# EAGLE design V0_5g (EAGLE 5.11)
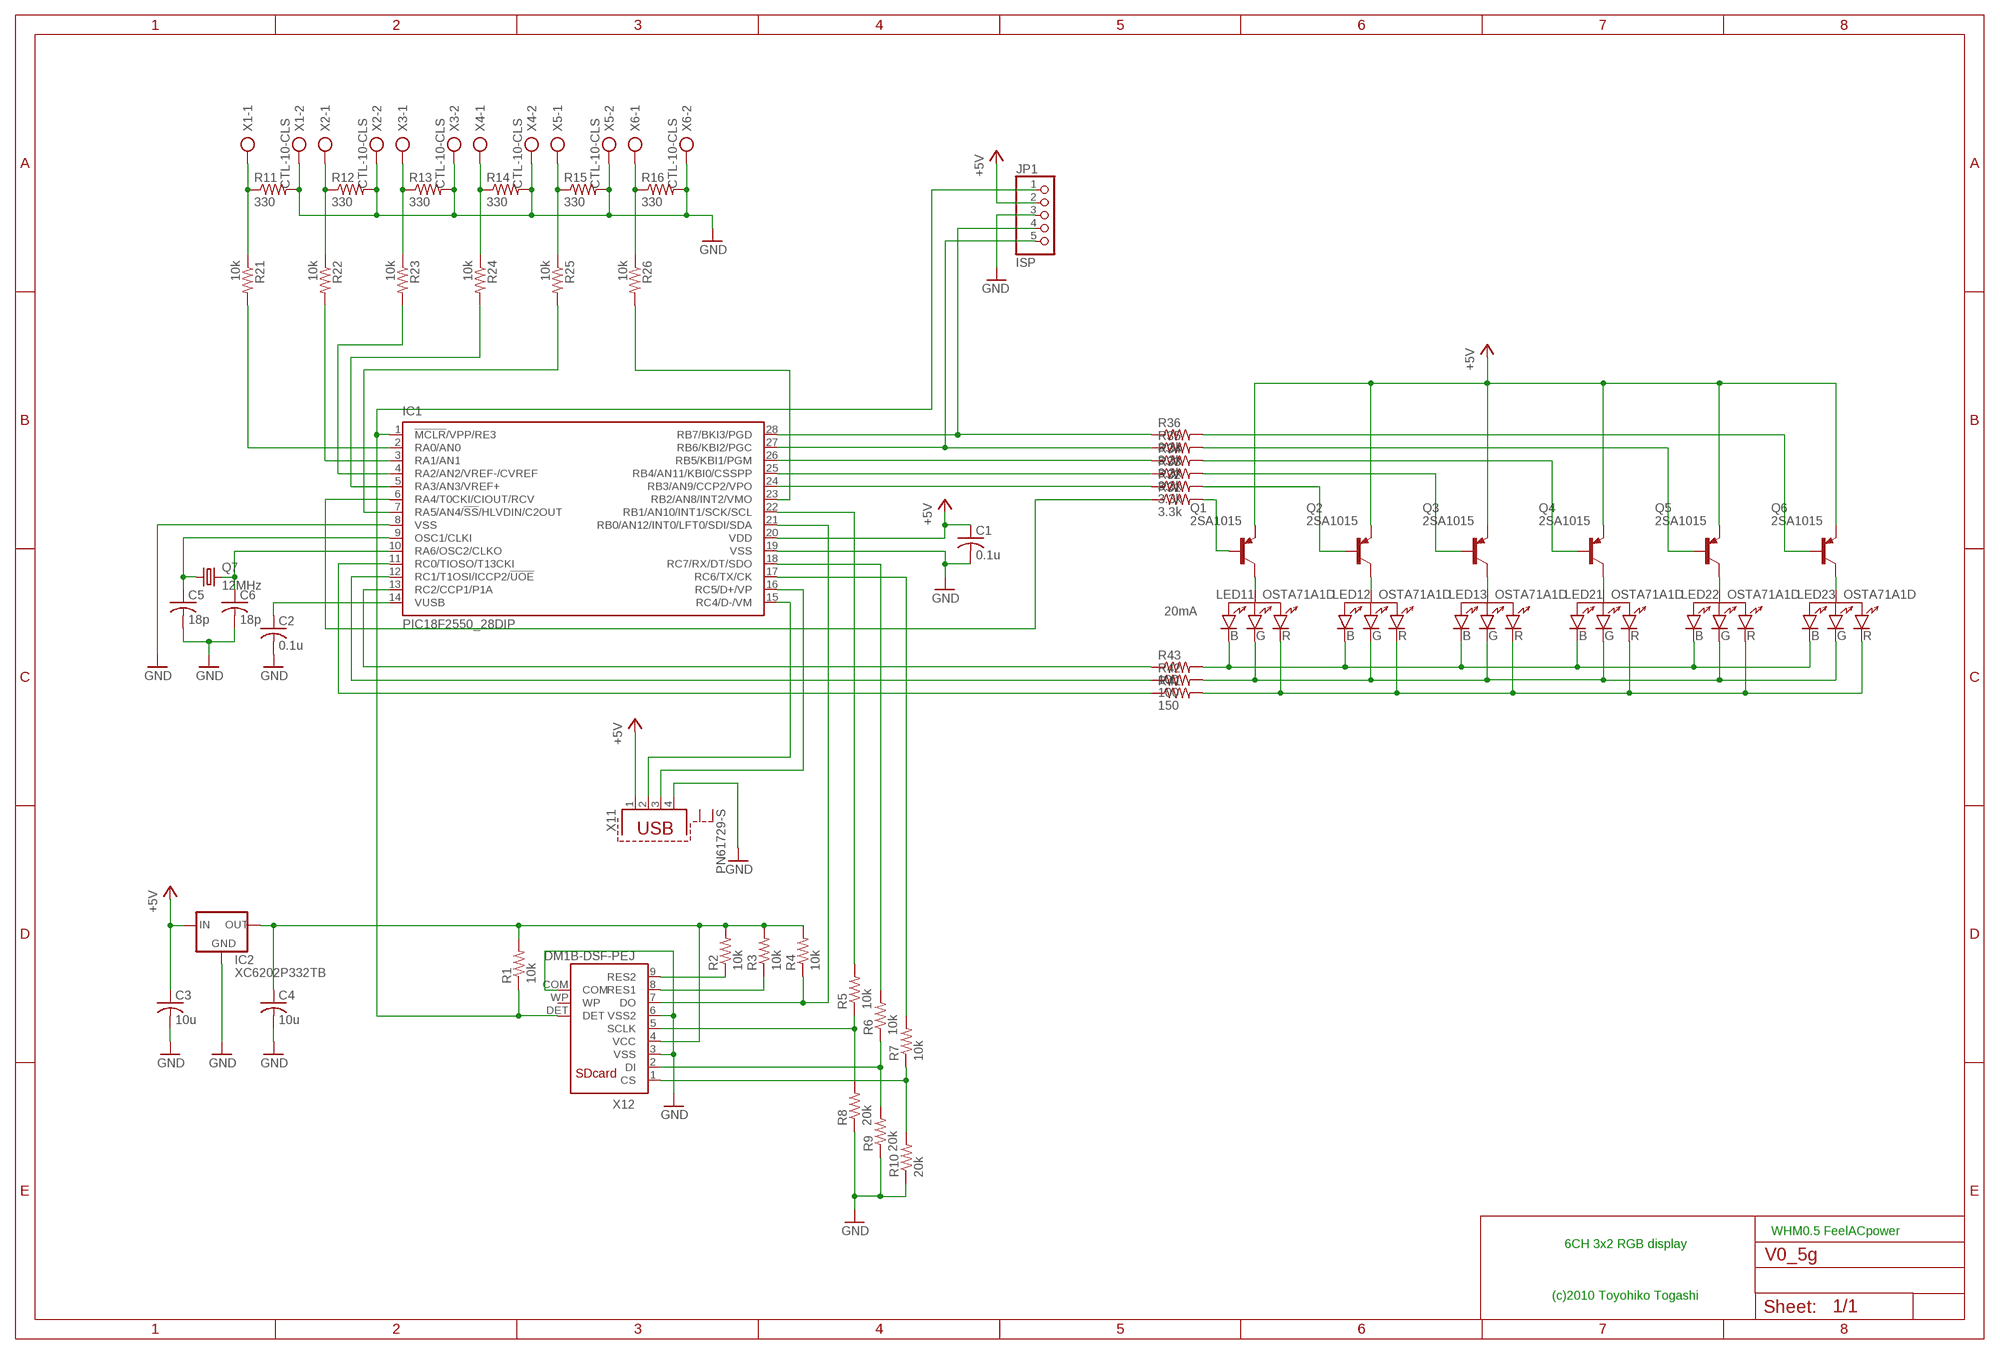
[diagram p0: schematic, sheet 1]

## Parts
C1  0.1u  C-US025-025X050  [C025-025X050]
C2  0.1u  C-US025-025X050  [C025-025X050]
C3  10u  C-US025-025X050  [C025-025X050]
C4  10u  C-US025-025X050  [C025-025X050]
C5  18p  C-US025-024X044  [C025-024X044]
C6  18p  C-US025-024X044  [C025-024X044]
IC1  PIC18F2550_28DIP  [DIL28-3]
IC2  XC6202P332TB  78LXX  [78LXX]
JP1  ISP  PINHD-1X5  [1X05]
LED11  OSTA71A1D  [FLUX-LED]
LED12  OSTA71A1D  [FLUX-LED]
LED13  OSTA71A1D  [FLUX-LED]
LED21  OSTA71A1D  [FLUX-LED]
LED22  OSTA71A1D  [FLUX-LED]
LED23  OSTA71A1D  [FLUX-LED]
Q1  2SA1015  BF421  [TO92-BCE]
Q2  2SA1015  BF421  [TO92-BCE]
Q3  2SA1015  BF421  [TO92-BCE]
Q4  2SA1015  BF421  [TO92-BCE]
Q5  2SA1015  BF421  [TO92-BCE]
Q6  2SA1015  BF421  [TO92-BCE]
Q7  12MHz  CRYSTALHC49S  [HC49/S]
R1  10k  R-US_0204/7  [0204/7]
R2  10k  R-US_0204/7  [0204/7]
R3  10k  R-US_0204/7  [0204/7]
R4  10k  R-US_0204/7  [0204/7]
R5  10k  R-US_0204/7  [0204/7]
R6  10k  R-US_0204/7  [0204/7]
R7  10k  R-US_0204/7  [0204/7]
R8  20k  R-US_0204/7  [0204/7]
R9  20k  R-US_0204/7  [0204/7]
R10  20k  R-US_0204/7  [0204/7]
R11  330  R-US_0204/7  [0204/7]
R12  330  R-US_0204/7  [0204/7]
R13  330  R-US_0204/7  [0204/7]
R14  330  R-US_0204/7  [0204/7]
R15  330  R-US_0204/7  [0204/7]
R16  330  R-US_0204/7  [0204/7]
R21  10k  R-US_0204/7  [0204/7]
R22  10k  R-US_0204/7  [0204/7]
R23  10k  R-US_0204/7  [0204/7]
R24  10k  R-US_0204/7  [0204/7]
R25  10k  R-US_0204/7  [0204/7]
R26  10k  R-US_0204/7  [0204/7]
R31  3.3k  R-US_0204/5  [0204/5]
R32  3.3k  R-US_0204/5  [0204/5]
R33  3.3k  R-US_0204/5  [0204/5]
R34  3.3k  R-US_0204/7  [0204/7]
R35  3.3k  R-US_0204/7  [0204/7]
R36  3.3k  R-US_0204/7  [0204/7]
R41  150  R-US_0204/7  [0204/7]
R42  100  R-US_0204/7  [0204/7]
R43  100  R-US_0204/7  [0204/7]
X1  CTL-10-CLS  AK500/2  [AK500/2]
X2  CTL-10-CLS  AK500/2  [AK500/2]
X3  CTL-10-CLS  AK500/2  [AK500/2]
X4  CTL-10-CLS  AK500/2  [AK500/2]
X5  CTL-10-CLS  AK500/2  [AK500/2]
X6  CTL-10-CLS  AK500/2  [AK500/2]
X11  PN61729-S  [PN61729-S]
X12  DM1B-DSF-PEJ  [DM1B]

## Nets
+5V: C1.1 C3.1 IC1.20(VDD) IC2.IN JP1.2 Q1.E Q2.E Q3.E Q4.E Q5.E Q6.E X11.1
GND: C1.2 C2.2 C3.2 C4.2 C5.2 C6.2 IC1.8(VSS) IC1.19(VSS) IC2.GND JP1.3 R8.1 R9.1 R10.1 R11.2 R12.2 R13.2 R14.2 R15.2 R16.2 X1.2 X2.2 X3.2 X4.2 X5.2 X6.2 X11.4 X12.3(VSS) X12.6(VSS2) X12.COM
N$1: IC1.7(RA5/AN4/!SS!/HLVDIN/C2OUT) R25.2
N$2: IC1.5(RA3/AN3/VREF+) R24.2
N$3: IC1.4(RA2/AN2/VREF-/CVREF) R23.2
N$4: IC1.3(RA1/AN1) R22.2
N$5: C4.1 IC2.OUT R1.2 R2.2 R3.2 R4.2 X12.4(VCC)
N$6: R5.1 R8.2 X12.5(SCLK)
N$7: IC1.21(RB0/AN12/INT0/LFT0/SDI/SDA) R4.1 X12.7(DO)
N$8: R6.1 R9.2 X12.2(DI)
N$9: R7.1 R10.2 X12.1(CS)
N$10: IC1.1(!MCLR!/VPP/RE3) JP1.1 R1.1 X12.DET
N$11: LED21.P$1 Q4.C
N$13: LED22.P$1 Q5.C
N$14: IC1.25(RB4/AN11/KBI0/CSSPP) R33.1
N$15: LED12.P$1 Q2.C
N$16: IC1.15(RC4/D-/VM) X11.2
N$17: IC1.16(RC5/D+/VP) X11.3
N$18: LED13.P$1 Q3.C
N$19: LED23.P$1 Q6.C
N$20: IC1.22(RB1/AN10/INT1/SCK/SCL) R5.2
N$21: IC1.18(RC7/RX/DT/SDO) R6.2
N$22: IC1.17(RC6/TX/CK) R7.2
N$23: IC1.6(RA4/T0CKI/CIOUT/RCV) R31.1
N$24: Q4.B R34.2
N$25: IC1.11(RC0/TIOSO/T13CKI) R41.1
N$26: IC1.26(RB5/KBI1/PGM) R34.1
N$27: IC1.12(RC1/T1OSI/ICCP2/!UOE) R42.1
N$28: IC1.13(RC2/CCP1/P1A) R43.1
N$29: IC1.23(RB2/AN8/INT2/VMO) R26.2
N$30: IC1.28(RB7/BKI3/PGD) JP1.4 R36.1
N$31: IC1.27(RB6/KBI2/PGC) JP1.5 R35.1
N$33: Q1.B R31.2
N$35: Q2.B R32.2
N$37: R16.1 R26.1 X6.1
N$38: R15.1 R25.1 X5.1
N$39: R14.1 R24.1 X4.1
N$40: R13.1 R23.1 X3.1
N$41: R12.1 R22.1 X2.1
N$42: R2.1 X12.9(RES2)
N$43: R3.1 X12.8(RES1)
N$44: R11.1 R21.1 X1.1
N$45: Q3.B R33.2
N$46: Q5.B R35.2
N$47: C6.1 IC1.10(RA6/OSC2/CLKO) Q7.2
N$48: Q6.B R36.2
N$49: C5.1 IC1.9(OSC1/CLKI) Q7.1
N$50: IC1.2(RA0/AN0) R21.2
N$52: C2.1 IC1.14(VUSB)
N$55: LED11.P$1 Q1.C
N$56: LED11.P$2 LED12.P$2 LED13.P$2 LED21.P$2 LED22.P$2 LED23.P$2 R43.2
N$58: LED11.P$4 LED12.P$4 LED13.P$4 LED21.P$4 LED22.P$4 LED23.P$4 R41.2
N$59: LED11.P$3 LED12.P$3 LED13.P$3 LED21.P$3 LED22.P$3 LED23.P$3 R42.2
N$65: IC1.24(RB3/AN9/CCP2/VPO) R32.1
Unconnected: X11.S1 X11.S2 X12.WP

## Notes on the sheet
- 20mA
- WHM0.5 FeelACpower
- 6CH 3x2 RGB display
- (c)2010 Toyohiko Togashi

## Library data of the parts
C1-C6 = rcl:C-US: CAPACITOR, American symbol
IC1 = microchip:PIC18F2*_28: USB Microcontrollers with nanoWatt Technology High-Performance, Enhanced Flash, 28/40/44-Pin, Source: http://ww1.microchip.com/downloads/en/devicedoc/39632c.pdf
IC2 = v-reg:78LXX: VOLTAGE REGULATOR
JP1 = pinhead:PINHD-1X5: PIN HEADER
LED11-LED13 LED21-LED23 = TOG:OSTA71A1D: Super Flux RGB LED
Q1-Q6 = transistor-pnp:BF421*: PNP Transistror
Q7 = crystal:CRYSTAL: CRYSTAL; OC_FARNELL: 1667008; OC_NEWARK: unknown
R1-R16 R21-R26 R31-R36 R41-R43 = rcl:R-US_: RESISTOR, American symbol
X1-X6 = con-ptr500:AK500/2: CONNECTOR
X11 = con-berg:PN61729-S: BERG USB connector
X12 = TOG:DM1B-DSF-PEJ: SDcard connector reverse type HIROSE

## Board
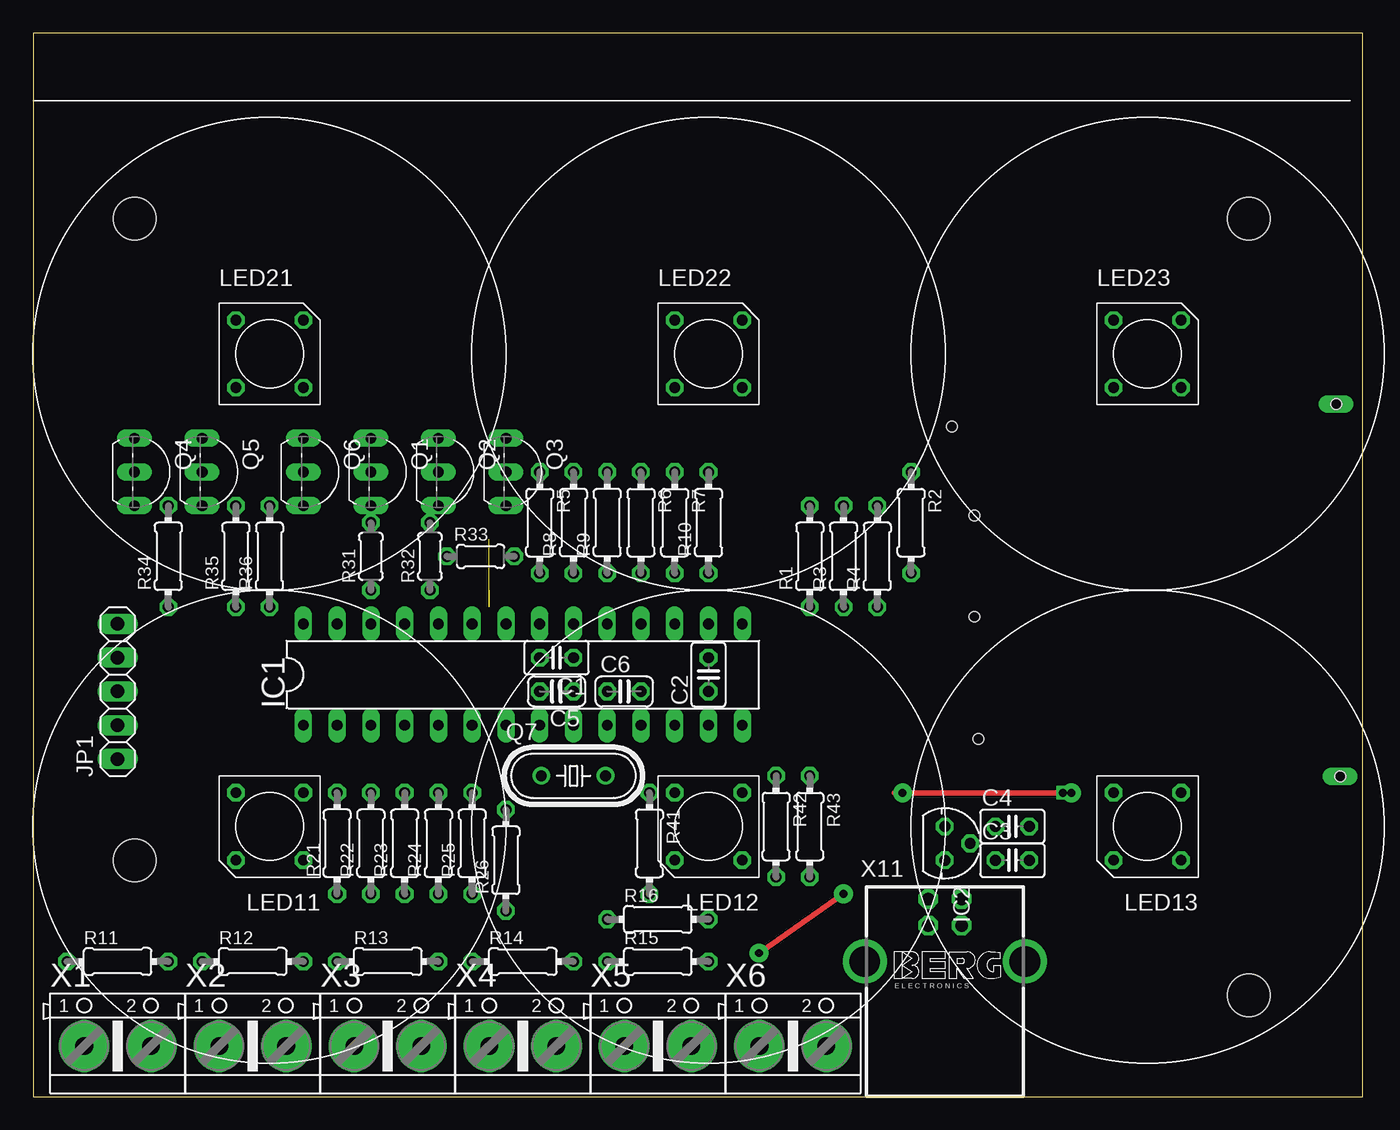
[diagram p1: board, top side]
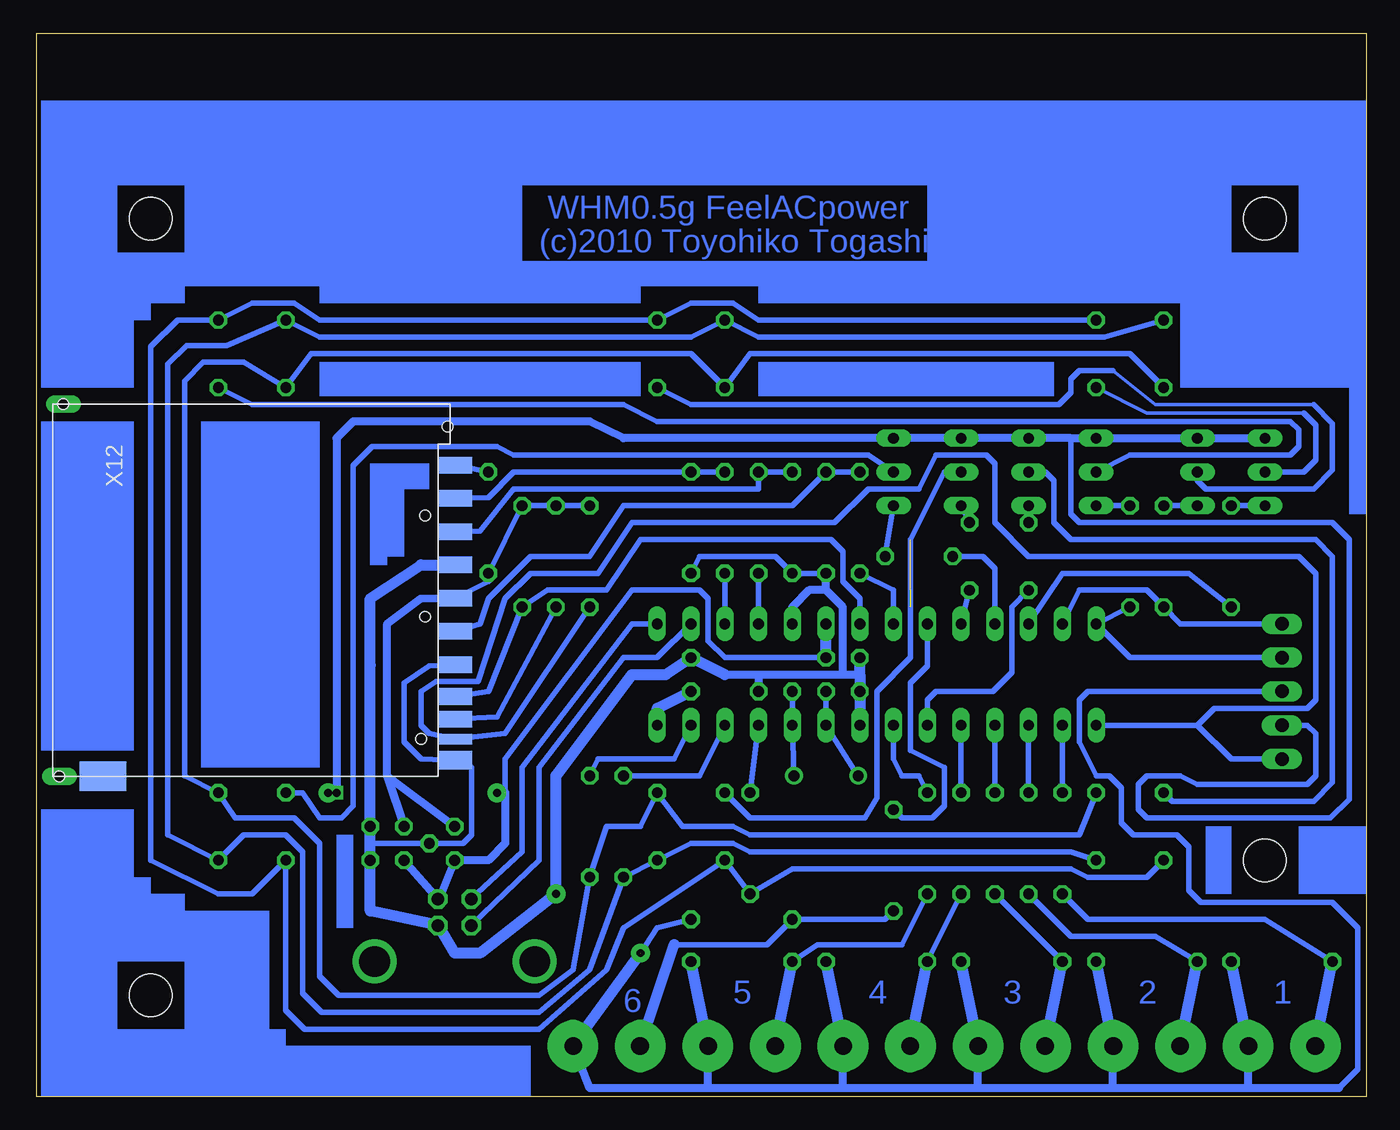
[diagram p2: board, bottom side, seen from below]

Size 100 x 80 mm. Coordinates in mm from the lower left corner, seen from the top.
Outline: 0,0 100,0 100,80 0,80 0,0
Copper layers (1*16): Top 0.035mm / dielectric 1.5mm / Bottom 0.035mm
Design rules "default": minimum track width 10mil, minimum drill 24mil, track to track 8mil, track to pad 8mil, pad to pad 8mil, via to via 8mil, smd to smd 8mil, copper to edge 40mil, drill to drill 8mil, minimum pad ring 10mil, minimum via ring 8mil, stop-mask expansion 4mil, vias tented up to drill 0mil, thermal gap 10mil
Holes 3.2 mm at 7.62,17.78 91.44,7.62 91.44,66.04 7.62,66.04

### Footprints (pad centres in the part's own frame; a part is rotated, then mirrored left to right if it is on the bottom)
C025-025X050 = drill 0.813 octagon: 1 -1.27,0; 2 1.27,0
C025-024X044 = drill 0.813 octagon: 1 -1.27,0; 2 1.27,0
DIL28-3 = drill 0.813 long: 1 -16.51,-3.81; 2 -13.97,-3.81; 3 -11.43,-3.81; 4 -8.89,-3.81; 5 -6.35,-3.81; 6 -3.81,-3.81; 7 -1.27,-3.81; 8 1.27,-3.81; 9 3.81,-3.81; 10 6.35,-3.81; 11 8.89,-3.81; 12 11.43,-3.81; 13 13.97,-3.81; 14 16.51,-3.81; 15 16.51,3.81; 16 13.97,3.81; 17 11.43,3.81; 18 8.89,3.81; 19 6.35,3.81; 20 3.81,3.81; 21 1.27,3.81; 22 -1.27,3.81; 23 -3.81,3.81; 24 -6.35,3.81; 25 -8.89,3.81; 26 -11.43,3.81; 27 -13.97,3.81; 28 -16.51,3.81
78LXX = drill 0.813 octagon: GND 0,1.905; IN 1.27,0; OUT -1.27,0
1X05 = drill 1.016 long: 1 -5.08,0; 2 -2.54,0; 3 0,0; 4 2.54,0; 5 5.08,0
FLUX-LED = drill 0.8 octagon: P$1 2.54,-2.54; P$2 -2.54,-2.54; P$3 -2.54,2.54; P$4 2.54,2.54
TO92-BCE = drill 0.813 long: B 2.54,0; C 0,0; E -2.54,0
HC49/S = drill 0.813 round: 1 -2.413,0; 2 2.413,0
0204/7 = drill 0.813 octagon: 1 -3.81,0; 2 3.81,0
0204/5 = drill 0.813 octagon: 1 -2.54,0; 2 2.54,0
AK500/2 = drill 1.321 long: 1 -2.515,0; 2 2.515,0
PN61729-S = drill 0.95 octagon: 1 1.25,4.71; 2 -1.25,4.71; 3 -1.25,2.71; 4 1.25,2.71 | drill 2.3 pad 2.9 round: S1 -6.02,0; S2 6.02,0
DM1B = smd 1.25 x 2.5: 1 -6.9,15.3; 2 -4.4,15.3; 3 -1.9,15.3; 4 0.6,15.3; 5 3.1,15.3; 6 5.6,15.3; 7 8,15.3; 8 9.7,15.3; 9 -9.4,15.3 | smd 1.4 x 2.5: COM 12.8,15.3 | smd 0.8 x 2.5: DET 11.2,15.3 | drill 0.8 pad 1.2 long: P$17 14,-14.5 | drill 0.8 pad 1.27 long: P$18 -14,-14.2 | smd 2.2 x 3.5: WP 14,-11.2 | hole 0.8: -12.3,14.7; -5.6,13; 2,13; 11.2,12.7; -14,-14.2; 14,-14.5

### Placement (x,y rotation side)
C1  39.37,33.02 180 top
C2  50.8,31.75 90 top
C3  73.66,17.78 0 top
C4  73.66,20.32 0 top
C5  39.37,30.48 180 top
C6  44.45,30.48 0 top
IC1  36.83,31.75 0 top
IC2  68.58,19.05 270 top
JP1  6.35,30.48 90 top
LED11  17.78,20.32 180 top
LED12  50.8,20.32 180 top
LED13  83.82,20.32 180 top
LED21  17.78,55.88 0 top
LED22  50.8,55.88 0 top
LED23  83.82,55.88 0 top
Q1  25.4,46.99 270 top
Q2  30.48,46.99 270 top
Q3  35.56,46.99 270 top
Q4  7.62,46.99 270 top
Q5  12.7,46.99 270 top
Q6  20.32,46.99 270 top
Q7  40.64,24.13 0 top
R1  58.42,40.64 90 top
R2  66.04,43.18 270 top
R3  60.96,40.64 90 top
R4  63.5,40.64 90 top
R5  38.1,43.18 270 top
R6  45.72,43.18 270 top
R7  48.26,43.18 270 top
R8  40.64,43.18 90 top
R9  43.18,43.18 90 top
R10  50.8,43.18 90 top
R11  6.35,10.16 0 top
R12  16.51,10.16 0 top
R13  26.67,10.16 0 top
R14  36.83,10.16 0 top
R15  46.99,10.16 0 top
R16  46.99,13.34 0 top
R21  22.86,19.05 90 top
R22  25.4,19.05 90 top
R23  27.94,19.05 90 top
R24  30.48,19.05 90 top
R25  33.02,19.05 90 top
R26  35.56,17.78 90 top
R31  25.4,40.64 90 top
R32  29.84,40.64 90 top
R33  33.66,40.64 0 top
R34  10.16,40.64 90 top
R35  15.24,40.64 90 top
R36  17.78,40.64 90 top
R41  46.35,19.05 270 top
R42  55.88,20.32 270 top
R43  58.42,20.32 270 top
X1  6.35,3.81 0 top
X2  16.51,3.81 0 top
X3  26.67,3.81 0 top
X4  36.83,3.81 0 top
X5  46.99,3.81 0 top
X6  57.15,3.81 0 top
X11  68.58,10.16 0 top
X12  83.82,38.1 270 bottom

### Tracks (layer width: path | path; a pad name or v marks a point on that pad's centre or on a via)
+5V  (via drill 0.6)  (1 unrouted)
  Top 0.406: v77.47,22.86 64.77,22.86
  Bottom 0.406: C1.1 48.26,33.02 49.53,34.29 49.53,37.47 50.16,38.1 55.24,38.1 64.77,25.4 64.77,22.86 | JP1.2 4.45,27.94 3.81,27.3 3.81,24.13 4.45,23.5 12.7,23.5 13.97,24.13 16.51,24.13 17.14,23.5 17.14,21.59 16.51,20.95 2.69,20.95 1.27,22.38 1.27,41.91 2.54,43.18 21.59,43.18 22.23,43.81 22.23,49.53 | 69.85,14.87 X11.1
  Bottom 0.61: Q4.E Q5.E Q6.E 22.23,49.53 Q1.E Q2.E Q3.E 55.88,49.53 58.42,50.8 76.2,50.8 77.47,49.53 v77.47,22.86 | 69.85,14.87 69.85,14.61 IC2.IN 66.04,17.78 64.77,19.05 64.77,22.86 | X11.1 C3.1
  Bottom 0.813: C1.1 IC1.20
GND  (via drill 0.6)  (1 unrouted)
  Top 0.406: 54.61,10.79 v60.96,15.24
  Bottom 0.406: 74.93,19.05 IC2.GND 67.94,19.05 67.31,19.68 67.31,24.77 X12.COM 71.12,25.4 72.39,26.67 72.39,31.11 70.48,32.38 X12.6 | R8.1 R9.1 44.45,40.64 50.16,40.64 R10.1 | JP1.3 20.95,30.48 21.59,29.84 21.59,26.67 20.32,24.13 19.31,24.13 18.41,23.23 18.41,20.58 17.52,19.68 14.23,19.68 13.34,18.79 13.34,15.5 12.44,14.61 2.54,14.61 0.64,12.7 0.64,2.06 2.06,0.64 | 54.61,10.79 53.34,12.7 R16.2
  Bottom 0.61: 8.89,0.64 X1.2 | 8.89,0.64 19.05,0.64 | 19.05,0.64 29.21,0.64 | 29.21,0.64 39.37,0.64 | 39.37,0.64 49.53,0.64 | 49.53,0.64 58.42,0.64 X6.2 | 19.05,0.64 X2.2 | 29.21,0.64 X3.2 | 39.37,0.64 X4.2 | 49.53,0.64 X5.2 | 2.06,0.64 8.89,0.64 | 48.26,31.75 45.72,31.75 | 45.72,31.75 C6.2 | 39.37,31.75 38.1,31.75 | 45.72,31.75 39.37,31.75 | 39.37,31.75 39.37,36.83 40.64,38.1 | 40.64,38.1 R8.1 | IC1.19 43.18,36.83 41.91,38.1 40.64,38.1
  Bottom 0.813: X5.2 R15.2 | X3.2 R13.2 | X2.2 R12.2 | X1.2 R11.2 | 48.26,31.75 C2.2 52.7,31.75 55.24,31.75 60.96,24.13 v60.96,15.24 66.67,10.79 68.58,10.79 X11.4 74.93,13.97 C3.2 74.93,19.05 C4.2 74.93,32.44 74.93,37.47 71.12,40.01 X12.3 | X4.2 R14.2 | X6.2 54.61,10.79 | IC1.8 C5.2 38.1,31.75 C1.2
N$1
  Bottom 0.406: R25.2 33.66,24.13 34.92,24.13 35.56,25.4 IC1.7
N$2
  Bottom 0.406: R24.2 IC1.5
N$3
  Bottom 0.406: R23.2 IC1.4
N$4
  Bottom 0.406: R22.2 IC1.3
N$5
  Bottom 0.406: X12.4 66.04,38.73 R2.2 R4.2 R3.2 R1.2
  Bottom 0.61: X12.4 71.12,37.47 73.66,35.56 73.66,24.13 | 73.66,24.13 C4.1 | IC2.OUT 73.66,24.13
N$6
  Bottom 0.406: R5.1 R8.2 43.18,44.45 55.88,44.45 58.42,40.64 62.87,40.64 66.04,37.47 66.67,35.56 X12.5
N$7
  Bottom 0.406: IC1.21 38.1,37.47 39.37,38.73 39.37,41.01 40.27,41.91 54.61,41.91 57.15,38.1 61.59,38.1 R4.1 66.04,30.48 X12.7
N$8
  Bottom 0.406: R9.2 R6.1 45.72,45.72 64.14,45.72 66.67,42.55 X12.2
N$9
  Bottom 0.406: R7.1 R10.2 64.14,46.99 66.04,45.09 X12.1
N$10
  Bottom 0.406: 12.7,27.94 11.43,29.21 4.45,29.21 3.81,29.84 3.81,39.37 5.08,40.64 25.4,40.64 27.94,43.18 27.94,47.62 28.57,48.26 32.38,48.26 33.66,45.72 37.47,45.72 40.01,43.18 55.24,43.18 57.78,39.37 62.87,39.37 64.77,37.47 66.8,31.24 69.98,31.24 71.12,30.48 71.12,27.94 70.48,27.3 X12.DET 64.77,27.3 R1.1 | 12.7,27.94 IC1.1 | JP1.1 10.16,25.4 12.7,27.94
N$11
  Bottom 0.254: LED21.P$1 16.51,51.44 4.71,51.44
  Bottom 0.406: Q4.C 4.71,46.99 3.81,47.89 3.81,50.54 4.71,51.44
N$12  (via drill 0.6 pad 1.42)
  other vias: 78.11,22.86 78.11,22.86 91.44,7.62 91.44,66.04 7.62,66.04 7.62,17.78
N$13
  Bottom 0.254: 3.96,52.07 15.88,52.07 19.05,54.61
  Bottom 0.406: LED22.P$1 50.8,52.07 23.12,52.07 22.23,52.97 22.23,53.98 21.59,54.61 19.05,54.61 | 3.96,52.07 2.54,50.65 2.54,47.14 3.96,45.72 12.06,45.72 12.7,46.35 Q5.C
N$14
  Bottom 0.406: R33.1 28.84,40.64 27.94,39.74 IC1.25
N$15  (3 unrouted)
  Bottom 0.406: LED12.P$1 46.35,20.95 37.73,20.95 36.83,22.49 36.83,30.48 34.29,33.02 34.29,41.91 31.75,46.99 Q2.C
N$16
  Bottom 0.406: X11.2 63.5,18.41 63.5,24.77 55.24,35.56 IC1.15
N$17
  Bottom 0.406: X11.3 62.23,17.78 62.23,24.77 55.88,33.02 53.34,33.02 IC1.16
N$18
  Bottom 0.406: LED13.P$1 80.01,22.86 78.74,20.95 77.1,20.95 76.2,21.85 76.2,47.48 74.78,48.9 65.41,48.9 64.14,48.26 37.47,48.26 Q3.C
N$19
  Bottom 0.406: LED23.P$1 83.82,52.07 55.88,52.07 53.34,50.8 5.71,50.8 5.08,50.16 5.08,48.9 5.71,48.26 17.78,48.26 Q6.C
N$20
  Bottom 0.406: R5.2 35.56,38.1 IC1.22
N$21
  Bottom 0.406: R6.2 IC1.18
N$22
  Bottom 0.406: R7.2 IC1.17
N$23
  Bottom 0.406: R31.1 26.67,36.83 26.67,31.9 28.09,30.48 32.38,30.48 33.02,29.84 IC1.6
N$24
  Bottom 0.406: R34.2 Q4.B
N$25
  Bottom 0.406: IC1.11 R41.1
N$26
  Bottom 0.406: IC1.26 22.86,39.37 13.34,39.37 R34.1
N$27
  Bottom 0.406: R42.1 50.16,24.13 IC1.12
N$28
  Bottom 0.406: R43.1 57.78,25.4 52.07,25.4 IC1.13
N$29
  Bottom 0.406: IC1.23 33.02,32.38 34.29,31.11 34.29,26.04 31.75,24.77 31.75,21.85 32.65,20.95 34.92,20.95 R26.2
N$30
  Bottom 0.406: R36.1 IC1.28 17.78,33.02 JP1.4
N$31
  Bottom 0.406: IC1.27 21.59,38.1 16.51,38.1 R35.1 13.97,35.56 JP1.5
N$32  (via drill 0.6 pad 1.42)
  other vias: 65.41,22.86
N$33
  Bottom 0.406: Q1.B R31.2
N$34  (via drill 0.6 pad 1.42)
  other vias: 54.61,10.79
N$35
  Bottom 0.406: Q2.B R32.2
N$36  (via drill 0.6 pad 1.42)
  other vias: 60.96,15.24
N$37
  Bottom 0.406: 52.07,11.43 45.09,11.43 R16.1 36.2,13.34 R26.1
  Bottom 0.813: X6.1 52.07,11.43
N$38
  Bottom 0.406: R15.1 41.27,11.43 34.92,11.43 R25.1
  Bottom 0.813: X5.1 R15.1
N$39
  Bottom 0.406: R14.1 R24.1
  Bottom 0.813: X4.1 R14.1
N$40
  Bottom 0.406: R23.1 R13.1
  Bottom 0.813: X3.1 R13.1
N$41
  Bottom 0.406: R22.1 22.23,12.06 15.88,12.06 R12.1
  Bottom 0.813: X2.1 R12.1
N$42
  Bottom 0.406: R2.1 X12.9
N$43
  Bottom 0.406: X12.8 65.41,28.57 R3.1
N$44
  Bottom 0.406: R21.1 20.95,13.34 7.62,13.34 R11.1
  Bottom 0.813: X1.1 R11.1
N$45
  Bottom 0.406: R33.2 Q3.B
N$46
  Bottom 0.406: R35.2 Q5.B
N$47
  Bottom 0.406: C6.1 IC1.10 Q7.2
N$48
  Bottom 0.406: R36.2 Q6.B
N$49
  Bottom 0.406: C5.1 IC1.9 Q7.1
N$50
  Bottom 0.406: R21.2 IC1.2
N$51  (via drill 0.8 pad 3.81)
  other vias: 3.81,3.81 59.69,3.81 8.89,3.81 13.97,3.81 19.05,3.81 24.13,3.81 29.21,3.81 34.29,3.81 39.37,3.81 44.45,3.81 49.53,3.81 54.61,3.81
N$52
  Bottom 0.813: IC1.14 53.34,29.21 C2.1
N$55
  Bottom 0.406: LED11.P$1 14.61,22.23 3.96,22.23 2.54,23.64 2.54,40.64 3.81,41.91 22.23,41.91 23.5,43.18 23.5,46.35 24.13,46.99 Q1.C
N$56
  Bottom 0.406: LED11.P$2 21.59,19.68 46.35,19.68 47.62,20.32 51.44,20.32 LED12.P$2 54.61,20.32 57.15,20.32 R43.2 59.69,9.53 62.23,7.62 77.32,7.62 78.74,9.04 78.74,19.05 80.64,20.95 85.09,20.95 LED13.P$2 88.9,24.13 88.9,53.83 87.48,55.24 84.45,55.24 LED23.P$2 79.38,55.88 50.8,55.88 LED22.P$2 46.35,55.88 17.78,55.88 LED21.P$2
N$58
  Bottom 0.406: LED11.P$4 16.51,16.51 20.95,16.51 22.23,17.14 43.18,17.14 R41.2 LED12.P$4 55.88,12.7 57.15,9.53 62.23,5.08 79.86,5.08 81.28,6.5 LED13.P$4 83.82,15.24 86.36,15.24 91.44,17.78 91.44,56.41 89.43,58.42 LED23.P$4 83.82,59.69 80.64,59.69 78.74,58.42 LED22.P$4 50.8,59.69 47.62,59.69 45.72,58.42 LED21.P$4
N$59
  Bottom 0.406: LED11.P$3 22.23,18.41 46.35,18.41 47.62,19.05 50.8,19.05 LED12.P$3 R42.2 58.42,9.53 62.23,6.35 78.59,6.35 80.01,7.77 80.01,18.41 81.28,19.68 84.45,19.68 LED13.P$3 90.17,19.68 90.17,55.09 88.75,56.52 85.72,56.52 LED23.P$3 78.74,57.15 50.8,57.15 LED22.P$3 45.72,57.15 19.68,57.15 LED21.P$3
N$65
  Bottom 0.406: IC1.24 R32.1
(copper drawn outside any net)
  shapes: Bottom area x30

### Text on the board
Bottom: WHM0.5g FeelACpower | (c)2010 Toyohiko Togashi | 1 | 2 | 3 | 4 | 5 | 6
